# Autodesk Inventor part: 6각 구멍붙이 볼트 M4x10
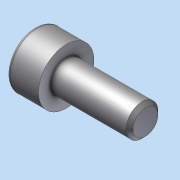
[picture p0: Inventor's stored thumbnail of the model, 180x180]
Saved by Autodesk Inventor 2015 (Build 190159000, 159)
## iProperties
Created: 2026-02
Part Number: 6각 구멍붙이 볼트 M4x10
Material: 일반
Document SubType Name: Modeling
Designer: Administrator
Density: 1 g/cm^3
Appearance: 기본값
Author: Administrator
Author: jhkim
Description: 6각머리 태핑 나사
Creation Date: 2026-01-30
Sending System: Autodesk Inventor 2026
Preprocessor: ST-DEVELOPER v20.1
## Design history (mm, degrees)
node "6각 구멍붙이 볼트 M4x101"
body "Solid1"
node "기준1"
